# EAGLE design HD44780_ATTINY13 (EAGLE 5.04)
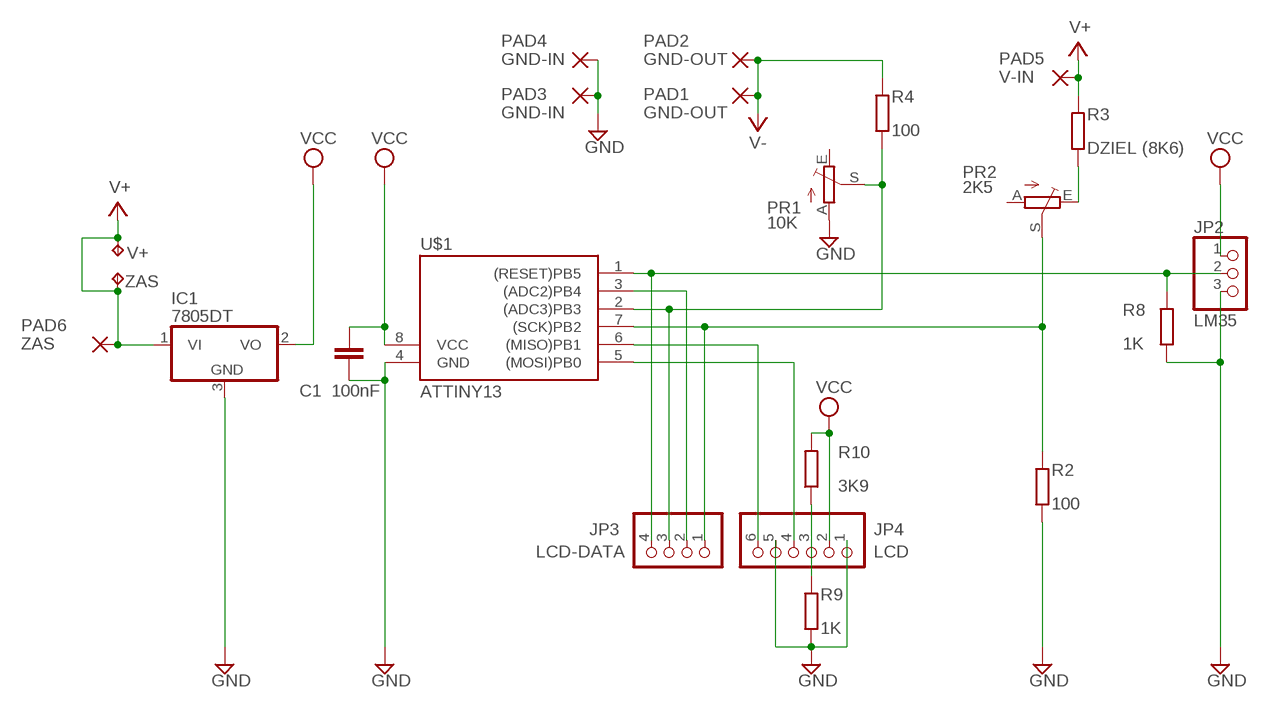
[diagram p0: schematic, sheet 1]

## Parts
C1  100nF  C-EUC0805  [C0805]
IC1  7805DT  [TO252]
JP2  LM35  PINHD-1X3  [1X03]
JP3  LCD-DATA  PINHD-1X4  [1X04]
JP4  LCD  PINHD-1X6  [1X06]
PAD1  GND-OUT  2,54/0,8  [2,54/0,8]
PAD2  GND-OUT  2,54/0,8  [2,54/0,8]
PAD3  GND-IN  2,54/0,8  [2,54/0,8]
PAD4  GND-IN  2,54/0,8  [2,54/0,8]
PAD5  V-IN  2,54/0,8  [2,54/0,8]
PAD6  ZAS  2,54/0,8  [2,54/0,8]
PR1  10K  TRIM_EU-CA6V  [CA6V]
PR2  2K5  TRIM_EU-CA6V  [CA6V]
R2  100  R-EU_R0805  [R0805]
R3  DZIEL (8K6)  R-EU_R0805  [R0805]
R4  100  R-EU_R0805  [R0805]
R8  1K  R-EU_R0805  [R0805]
R9  1K  R-EU_R0805  [R0805]
R10  3K9  R-EU_R0805  [R0805]
U$1  ATTINY13  TINY138S2  [SO08]
V+  TPTP08SQ  [TP08SQ]
ZAS  TPTP08SQ  [TP08SQ]

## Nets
GND: C1.2 IC1.3(GND) JP2.3 JP4.1 JP4.5 PAD3.1(P) PAD4.1(P) PR1.A R2.1 R8.1 R9.1 U$1.4(GND)
N$1: JP4.3 R9.2 R10.1
N$2: JP3.2 U$1.3((ADC2)PB4)
N$3: PR2.E R3.1
N$5: JP2.2 JP3.4 R8.2 U$1.1((RESET)PB5)
N$6: JP4.6 U$1.6((MISO)PB1)
N$7: JP4.4 U$1.5((MOSI)PB0)
N$10: JP3.3 PR1.S R4.1 U$1.2((ADC3)PB3)
N$12: JP3.1 PR2.S R2.2 U$1.7((SCK)PB2)
V+: IC1.1(VI) PAD5.1(P) PAD6.1(P) R3.2 V+.TP ZAS.TP
V-: PAD1.1(P) PAD2.1(P) R4.2
VCC: C1.1 IC1.2(VO) JP2.1 JP4.2 R10.2 U$1.8(VCC)
Unconnected: PR1.E PR2.A

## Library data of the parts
C1 = rcl:C-EU: CAPACITOR, European symbol
IC1 = linear:78*: Positive VOLTAGE REGULATOR Source: http://cache.national.com/ds/LM/LM78L05.pdf http://www.fairchildsemi.com/ds/LM/LM7805.pdf
JP2 = pinhead:PINHD-1X3: PIN HEADER
JP3 = pinhead:PINHD-1X4: PIN HEADER
JP4 = pinhead:PINHD-1X6: PIN HEADER
PAD1-PAD6 = wirepad:2,54/0,8: THROUGH-HOLE PAD
PR1 PR2 = pot:TRIM_EU-: POTENTIOMETER
R2-R4 R8-R10 = rcl:R-EU_: RESISTOR, European symbol
U$1 = avr-4:TINY13*
V+ ZAS = testpad:TP

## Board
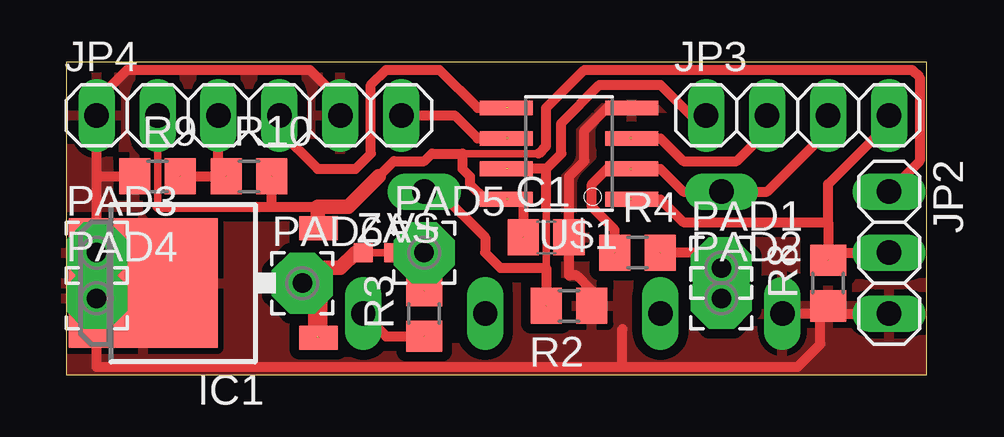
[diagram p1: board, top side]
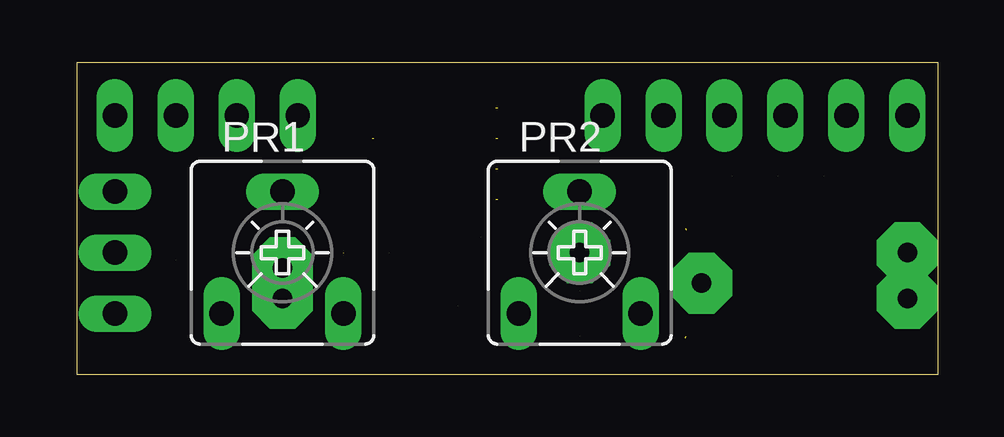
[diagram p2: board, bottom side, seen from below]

Size 35.86 x 13.01 mm. Coordinates in mm from the lower left corner, seen from the top.
Outline: 0,0 35.86,0 35.86,13.01 0,13.01 0,0
Copper layers (1*16): Top 0.035mm / dielectric 1.5mm / Bottom 0.035mm
Design rules "default *": minimum track width 10mil, minimum drill 24mil, track to track 16mil, track to pad 16mil, pad to pad 16mil, via to via 16mil, smd to smd 16mil, copper to edge 1mil, drill to drill 8mil, minimum pad ring 10mil, minimum via ring 8mil, stop-mask expansion 4mil, vias tented up to drill 0mil, thermal gap 10mil

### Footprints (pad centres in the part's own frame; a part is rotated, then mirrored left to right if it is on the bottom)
C0805 = smd 1.3 x 1.5: 1 -0.95,0; 2 0.95,0
TO252 = smd 1 x 1.6: 1 -2.28,-4.8; 2 2.28,-4.8 | smd 5.4 x 6.2: 3 0,2.5
1X03 = drill 1.016 long: 1 -2.54,0; 2 0,0; 3 2.54,0
1X04 = drill 1.016 long: 1 -3.81,0; 2 -1.27,0; 3 1.27,0; 4 3.81,0
1X06 = drill 1.016 long: 1 -6.35,0; 2 -3.81,0; 3 -1.27,0; 4 1.27,0; 5 3.81,0; 6 6.35,0
2,54/0,8 = drill 0.813 pad 2.54 octagon: 1 0,0
CA6V = drill 1.016 long: A -2.54,-2.54; E 2.54,-2.54; S 0,2.54
R0805 = smd 1.3 x 1.5: 1 -0.95,0; 2 0.95,0
SO08 = smd 0.61 x 2.21: 1 -1.905,-2.616; 2 -0.635,-2.616; 3 0.635,-2.616; 4 1.905,-2.616; 5 1.905,2.616; 6 0.635,2.616; 7 -0.635,2.616; 8 -1.905,2.616
TP08SQ = smd 0.8 x 0.8: TP 0,0

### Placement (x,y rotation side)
C1  20,5.71 0 top
IC1  5.71,3.81 90 top
JP2  34.29,5.08 270 top
JP3  30.48,10.79 0 top
JP4  7.62,10.79 0 top
PAD1  27.3,4.45 0 top
PAD2  27.3,3.18 0 top
PAD3  1.27,5.08 0 top
PAD4  1.27,3.18 0 top
PAD5  14.92,5.08 0 top
PAD6  9.84,3.81 0 top
PR1  27.3,5.08 0 bottom
PR2  14.92,5.08 0 bottom
R2  20.96,2.86 180 top
R3  14.92,2.54 90 top
R4  23.81,5.08 0 top
R8  31.75,3.81 90 top
R9  3.81,8.25 0 top
R10  7.62,8.25 0 top
U$1  20.96,9.21 90 top
V+  13.65,5.08 0 top
ZAS  12.38,5.08 0 top

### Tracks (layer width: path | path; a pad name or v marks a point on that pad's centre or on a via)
GND
  Top 0.406: 31.75,2.54 31.43,2.54 31.43,1.27 30.48,0.32 20.32,0.32 | 31.75,2.54 JP2.3 | 20.32,0.32 23.18,0.32 23.18,1.9 | 23.5,11.11 22.54,11.11 21.59,10.16 21.59,8.89 20.96,8.25 20.96,4.13 21.27,4.13 21.91,3.49 R2.1 | JP4.5 11.43,11.43 10.16,12.7 2.54,12.7 1.27,11.43 JP4.1 1.27,8.25 | 1.27,3.81 PAD4.1 1.27,0.32 20.32,0.32 | 1.27,3.81 3.18,3.81 | 1.27,3.81 PAD3.1 1.27,8.25 | 1.27,8.25 R9.1 | 31.75,2.54 PR1.A
  pour Top: 0,12.38 35.88,12.38 35.88,0 0,0
N$1  (2 unrouted)
  Top 0.406: 6.35,8.25 JP4.3 | 6.35,8.25 R10.1 | R9.2 6.35,8.25
N$2  (1 unrouted)
  Top 0.406: JP3.2 29.21,10.16 27.94,8.89 25.72,8.89 24.77,9.84 23.5,9.84
N$3  (1 unrouted)
  Top 0.406: PR2.E 13.33,1.59 R3.1
N$5  (2 unrouted)
  Top 0.406: JP3.4 34.29,10.48 31.75,7.94 31.75,7.3 31.75,6.35 | 31.75,6.35 25.72,6.35 24.77,7.3 23.5,7.3 | 31.75,5.08 JP2.2 | 31.75,5.08 R8.2 | 31.75,6.35 31.75,5.08
N$6  (1 unrouted)
  Top 0.406: JP4.6 16.19,10.79 17.14,9.84 18.42,9.84
N$7  (1 unrouted)
  Top 0.406: JP4.4 8.89,10.16 10.48,8.57 12.06,8.57 12.7,9.21 12.7,12.07 13.33,12.7 15.56,12.7 17.14,11.11 18.42,11.11
N$10  (2 unrouted)
  Top 0.406: JP3.3 31.75,10.16 29.21,7.62 PR1.S 25.72,7.62 24.77,8.57 23.5,8.57 22.54,8.57 21.91,7.94 21.91,6.98 22.86,6.03 R4.1
N$12  (2 unrouted)
  Top 0.305: 20,4.45 20,6.98
  Top 0.406: JP3.1 26.04,10.79 24.77,12.07 22.23,12.07 20.64,10.48 20.64,9.21 20,8.57 | 20,8.57 18.42,8.57 18.1,8.57 | R2.2 20,4.45 18.1,4.45 17.46,5.08 17.46,5.71 15.56,7.62 PR2.S | 20,6.98 20,8.57
V+  (2 unrouted)
  Top 0.305: ZAS.TP V+.TP
  Top 0.406: 14.92,4.76 14.92,4.45 | PAD5.1 14.92,4.76 | 14.92,4.76 R3.2
  Top 0.61: V+.TP PAD5.1 | PAD6.1 10.48,4.45 11.43,4.45 12.06,5.08 ZAS.TP
  Top 0.813: PAD6.1 10.48,3.18 10.48,1.59
V-  (1 unrouted)
  Top 0.406: R4.2 26.67,5.08 PAD1.1 PAD2.1
VCC  (4 unrouted)
  Top 0.305: 3.81,6.98 3.81,9.53 3.81,9.84 | 16.51,9.21 19.69,9.21
  Top 0.406: C1.1 19.05,7.3 18.42,7.3 17.46,7.3 16.83,7.94 16.83,8.25 16.51,8.57 16.51,9.21 15.24,9.21 14.92,8.89 13.65,8.89 13.02,8.25 | 3.81,6.98 8.57,6.98 | 8.57,6.98 10.48,6.98 | 19.69,9.21 20,9.53 20,11.11 21.59,12.7 35.24,12.7 35.56,12.38 35.56,8.89 JP2.1 | 8.57,6.98 R10.2 | 3.81,9.53 JP4.2
  Top 0.61: 13.02,8.25 11.75,6.98 10.48,6.98 10.48,6.03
